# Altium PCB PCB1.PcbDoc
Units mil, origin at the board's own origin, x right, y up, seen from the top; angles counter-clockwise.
Board outline 5505 x 1975 mil, 4 copper layers (SIG_1, GND, GND-PWR, SIG_2), stack 23.712 mil thick; 82 components, 46 nets, 222 pads, 73 vias.
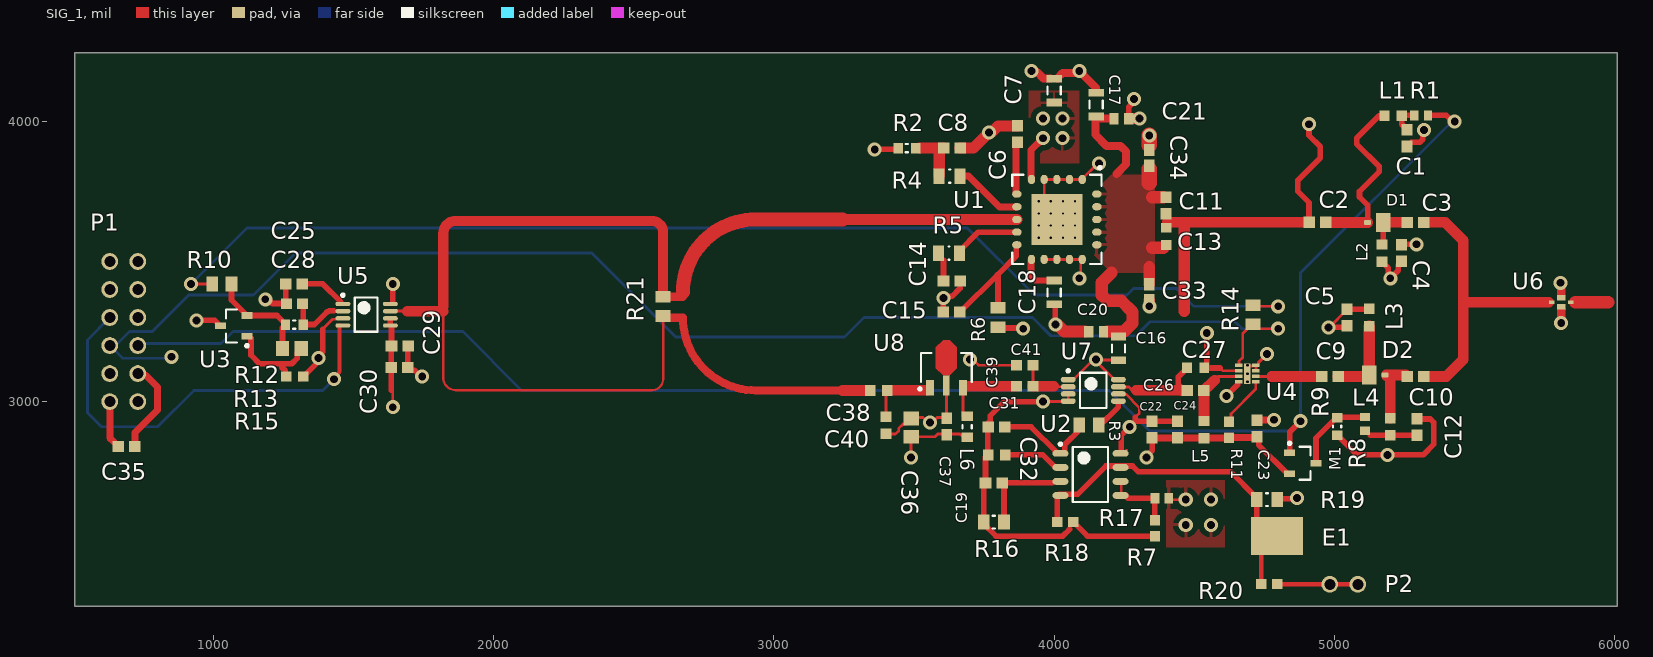
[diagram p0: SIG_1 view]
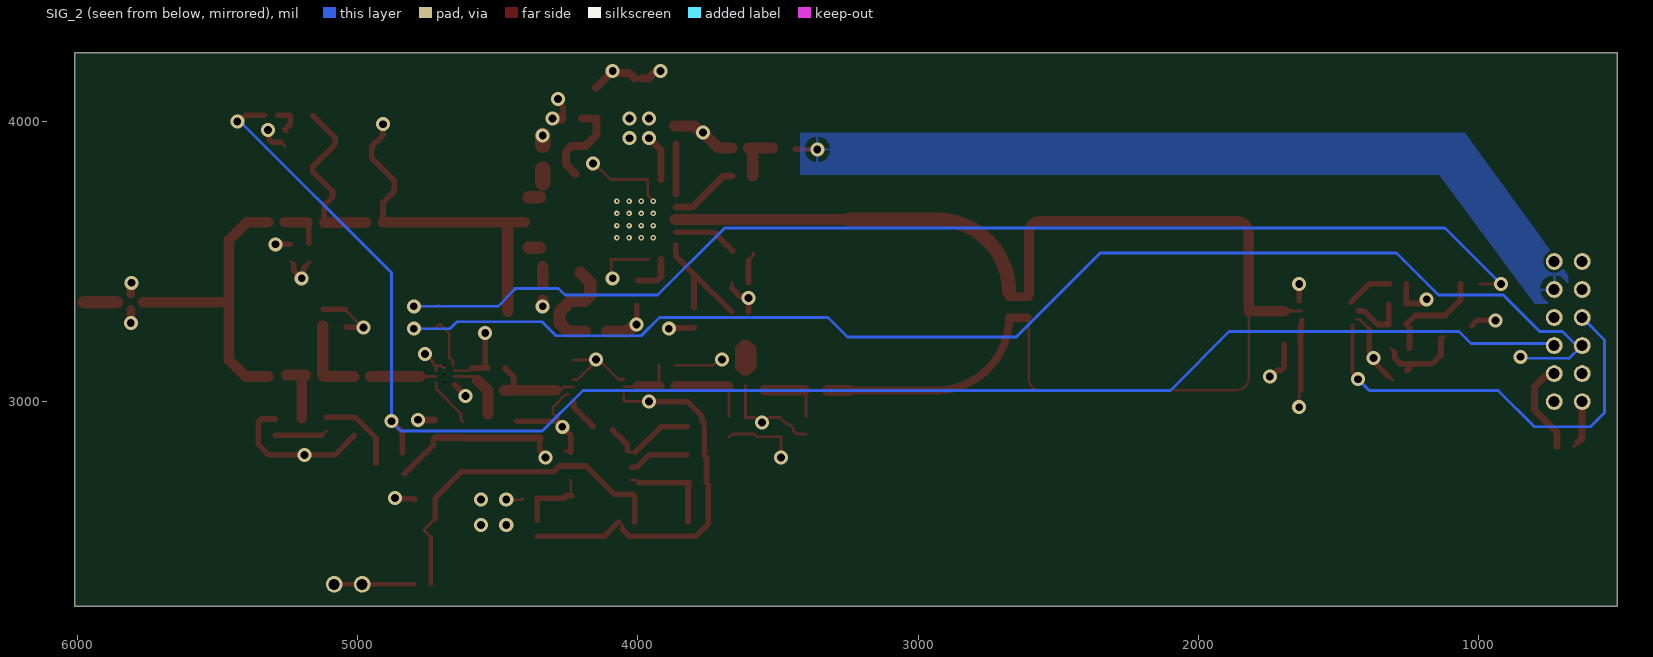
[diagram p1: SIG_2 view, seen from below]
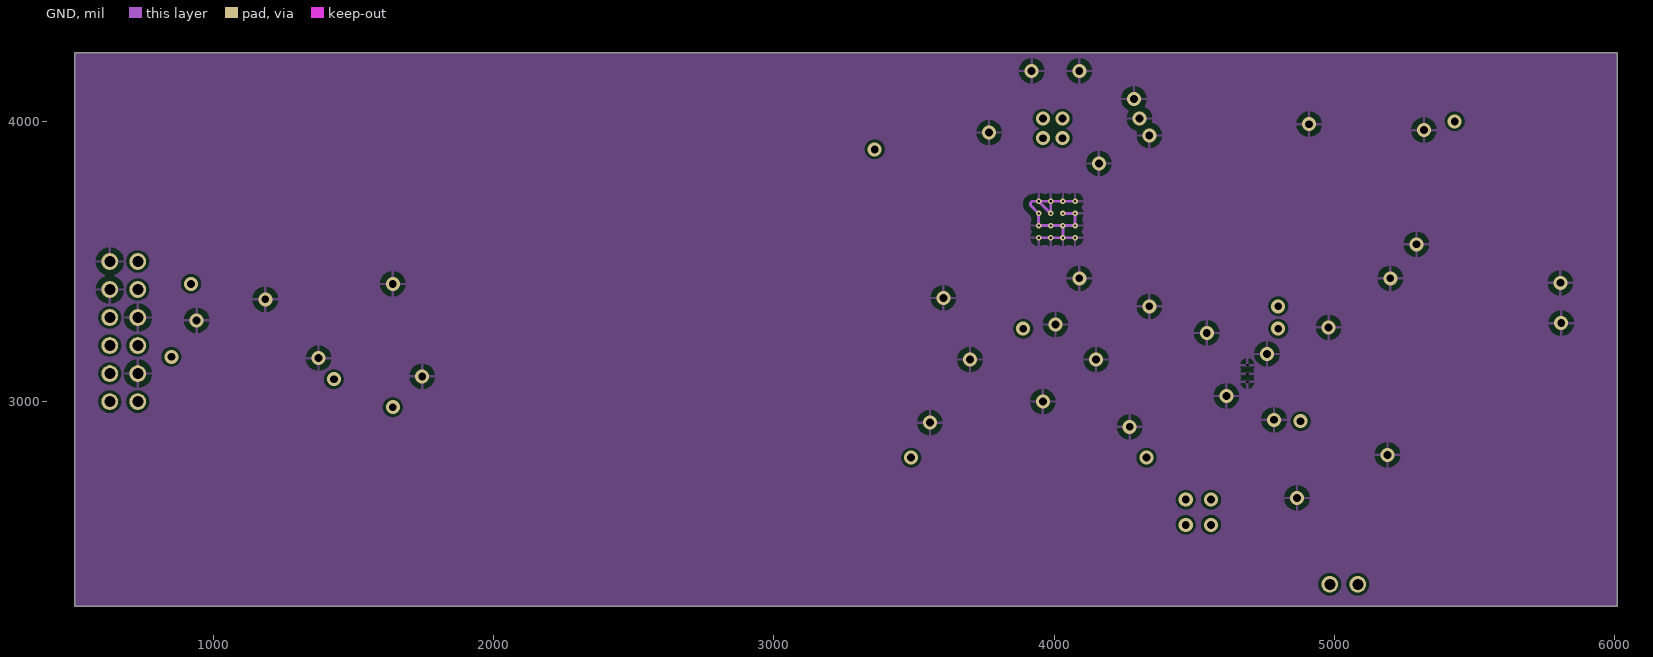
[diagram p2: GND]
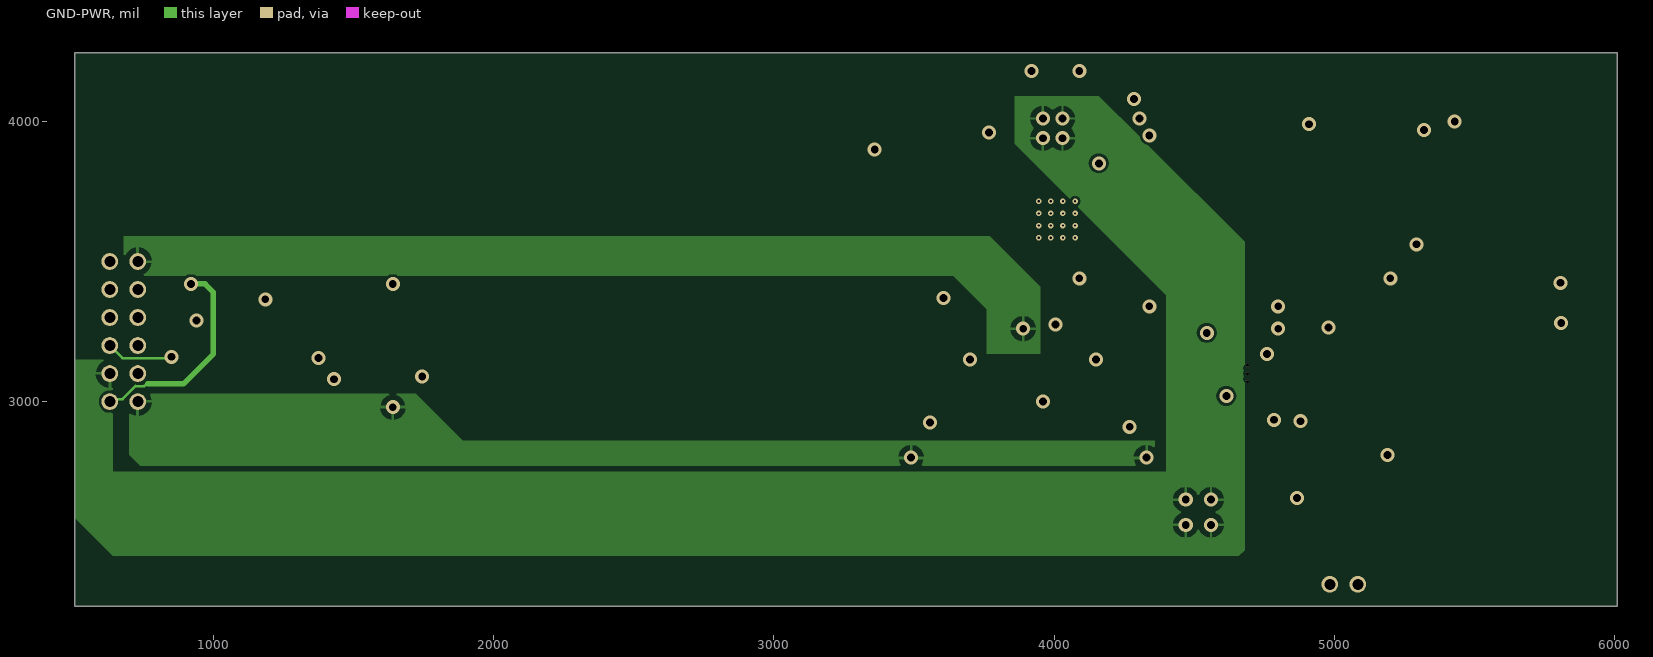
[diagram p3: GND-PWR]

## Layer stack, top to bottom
SIG_1: signal copper 1.378
Dielectric 2: prepreg 2.8, PP-006, Dk 4.1
GND: signal copper 1.378
Dielectric 1: dielectric 12.6, FR-4, Dk 4.8
GND-PWR: signal copper 1.378
Dielectric 3: prepreg 2.8, PP-006, Dk 4.1
SIG_2: signal copper 1.378

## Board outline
505,2270 505,4245 6010,4245 6010,2270

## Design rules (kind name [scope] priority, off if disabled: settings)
Clearance Clearance_1 [All] p1: gap=10 ignorepadtopadclearanceinfootprint=TRUE except(0: Arc-Hole Track-Hole SMDPad-Hole THPad-Hole Via-Hole Fill-Hole Poly-Hole Region-Hole Text-Hole; 5: Arc-SMDPad Track-SMDPad SMDPad-SMDPad SMDPad-Text Fill-Text Poly-Text Region-Text; 6: THPad-Via Via-Via; 20: Arc-Fill Arc-Poly Arc-Region Track-Fill Track-Poly Track-Region SMDPad-Fill SMDPad-Poly SMDPad-Region Fill-Fill Fill-Poly Fill-Region Poly-Poly Poly-Region Region-Region)
PlaneConnect [All] p1: planeconnectstyle=Direct reliefexpansion=20 reliefentries=4 reliefconductorwidth=10 reliefairgap=20
PolygonConnect [All] p1: connectstyle=Relief reliefconductorwidth=10 reliefentries=4 polygonreliefangle="90 Angle" airgapwidth=20
RoomDefinition 33-1-001_R01 [InComponentClass('33-1-001_R01')] p1 off: confinementstyle=ConfineIn formatcopy=TRUE lockcomponents=FALSE outline 8825,45 14100,45 14100,2135 8825,2135
RoutingVias [All] p1: holewidth=28 width=50 viastyle="Through Hole" minholewidth=28 minwidth=50 maxholewidth=28 maxwidth=50
SilkToSilkClearance [All] p1: silktosilkclearance=5
SilkToSolderMaskClearance [IsPad] p1: minsilkscreentomaskgap=5 clearancetoexposedcopper=TRUE
SolderMaskExpansion [All] p1: expansion=4 istentingtop=FALSE
Width [All] p1: maxlimit=200 minlimit=5 preferedwidth=10
27 further rules are at their usual default settings.

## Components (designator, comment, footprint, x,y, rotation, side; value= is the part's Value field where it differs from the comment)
C1 "C00000013" C0603C101J5GAC7082 5260,3940 r270 top
C2 "C00000013" C0603C101J5GAC7082 4940,3640 r0 top
C3 "C00000013" C0603C101J5GAC7082 5289.53,3639.53 r0 top
C4 "C00000013" C0603C101J5GAC7082 5240,3530 r270 top
C5 "C00000013" C0603C101J5GAC7082 5045,3299.53 r270 top
C6 "C00000007" 06033D105KAT2A 3870,3954.53 r90 top
C7 "C00000003" C2012X5R1V106K125AC 4000,4110 r90 top
C8 "C00000007" 06033D105KAT2A 3635.47,3905 r0 top
C9 "C00000013" C0603C101J5GAC7082 4985,3089.53 r0 top
C10 "C00000013" C0603C101J5GAC7082 5289.53,3089.53 r0 top
C11 "C00000007" 06033D105KAT2A 4400,3700 r90 top
C12 "C00000013" C0603C101J5GAC7082 5295,2909.25 r90 top
C13 "C00000005" CBR06C508A5GAC 4400,3590 r90 top
C14 "C00000007" 06033D105KAT2A 3635,3430 r180 top
C15 "C00000007" 06033D105KAT2A 3634.53,3320 r0 top
C16 "C00000003" C2012X5R1V106K125AC 4230,3190 r90 top
C17 "C00000003" C2012X5R1V106K125AC 4150,4060 r270 top
C18 "C00000003" C2012X5R1V106K125AC 4000,3390 r90 top
C19 "C00000011" C0603C104K4RACTU 3785,2710 r0 top
C20 "C00000004" 06035U9R1BAT2A 4150,3250 r0 top
C21 "C00000004" 06035U9R1BAT2A 4240,4010 r180 top
C22 "C00000007" 06033D105KAT2A 4350,2900 r270 top
C23 "C00000013" C0603C101J5GAC7082 4725,2904.53 r270 top
C24 "C00000013" C0603C101J5GAC7082 4440,2900 r90 top
C25 "C00000011" C0603C104K4RACTU 1286.89,3420 r180 top
C26 "C00000008" GQM1875C2E1R6BB12D 4505,3040 r180 top
C27 "C00000005" CBR06C508A5GAC 4505.51,3120 r180 top
C28 "C00000001" C0603C184J3RACTU 1288.86,3350 r0 top
C29 "C00000012" C0603C221J3RACAUTO 1665,3197.63 r180 top
C30 "C00000012" C0603C221J3RACAUTO 1664.53,3121.97 r180 top
C31 "C00000007" 06033D105KAT2A 3795,2910 r0 top
C32 "C00000014" ML03510R8BAT2A 3795,2810 r0 top
C33 "C00000010" VJ0603D1R8BXCQJHT 4340,3390 r90 top
C34 "C00000010" VJ0603D1R8BXCQJHT 4340,3870 r270 top
C35 "C00000011" C0603C104K4RACTU 690,2840 r180 top
C36 "C00000017" EMK212B7105KG-T 3490,2907.05 r270 top
C37 "C00000016" C0603C102F4GACTU 3617,2911 r270 top
C38 "C00000014" ML03510R8BAT2A 3375,3040 r0 top
C39 "C00000015" VJ0603A1R5CXQCW1BC 3895,3055 r0 top
C40 "C00000014" ML03510R8BAT2A 3400,2915 r90 top
C41 "C00000015" VJ0603A1R5CXQCW1BC 3895,3130 r0 top
D1 "D00000001" SMP1334-084LF 5140,3640 r180 top
D2 "D00000001" SMP1334-084LF 5160,3094 r0 top
E1 "5016" 5016 4795.43,2520 r0 top
L1 "L00000001" ILC0603ER22NJ 5210,4020 r0 top
L2 "L00000001" ILC0603ER22NJ 5170,3530 r90 top
L3 "L00000001" ILC0603ER22NJ 5125,3300 r90 top
L4 "L00000001" ILC0603ER22NJ 5200,2910.24 r90 top
L5 "L00000001" ILC0603ER22NJ 4535,2900 r270 top
L6 "L00000002" LQW18AS8N7J00D 3690,2910 r270 top
M1 "BSS84" BSS84,215 4887.76,2780 r0 top
P1 "67997-112HLF" 67997-112HLF 630,3000 r90 top
P2 "2Pin_Header" 2Pin_Header 4984,2348 r0 top
R1 "R00000009" CR0603-JW-820ELF 5310,4021.57 r0 top
R2 "R00000008" ERJ-U3RD8200V 3475,3905 r0 top
R3 "R00000003" SFR10EZPF10R0 4125,2916.7 r180 top
R4 "R00000004" CRCW08055R10FKTA 3627.6,3805 r0 top
R5 "R00000004" CRCW08055R10FKTA 3625,3530 r0 top
R6 "R00000003" SFR10EZPF10R0 3800,3300 r90 top
R7 "R00000011" ESR03EZPJ432 4360,2548.54 r90 top
R8 "R00000009" CR0603-JW-820ELF 5110,2920.08 r90 top
R9 "R00000001" ERJ-UP3F8660V 5010,2911.22 r90 top
R10 "R00000005" CR0805-FX-1580ELF 1030,3420 r180 top
R11 "R00000011" ESR03EZPJ432 4625,2900 r270 top
R12 "R00000006" ERA-6AEB101V 1280,3190 r180 top
R13 "R00000001" ERJ-UP3F8660V 1288.86,3275 r180 top
R14 "R00000010" CR0805-JW-203ELF 4710,3310 r90 top
R15 "R00000007" "RN73H1JTTD43R7B25 - duplicate" 1290,3090 r180 top
R16 "R00000012" RK73H2ATTD3832F 3785,2570 r0 top
R17 "R00000013" RCS0603499RFKEA 4385,2655 r180 top
R18 "R00000011" ESR03EZPJ432 4040,2570 r180 top
R19 "R00000012" RK73H2ATTD3832F 4760,2650 r0 top
R20 "R00000011" ESR03EZPJ432 4768,2349 r180 top
R21 "R00000010" CR0805-JW-203ELF 2605,3340 r90 top
U1 "IC BLM9D2327-26B" BLM9D2327-26B 4010,3650 r270 top
U2 "IC LM2907" LM2907 4130,2740 r0 top
U3 "IC TL4051AQDBZR" TL4051AQDBZR 1072.24,3270 r180 top
U4 "IC QPL9503" QPL9503 4716.57,3117.72 r180 top
U5 "IC MAX 2750 VCO" MAX2750EUA+ 1530,3310 r0 top
U6 "DEA162495BT-1289A1" DEA162495BT-1289A1 5810,3355 r0 top
U7 "IC HMC213BMS8E" HMC213BMS8E 4140,3040 r0 top
U8 "SKY65162-70LF" SKY65162-70LF 3615.94,3120.87 r90 top

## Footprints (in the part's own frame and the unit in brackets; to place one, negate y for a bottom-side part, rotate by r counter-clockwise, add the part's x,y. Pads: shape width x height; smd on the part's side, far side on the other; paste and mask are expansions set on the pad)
2Pin_Header [mil] "2Pin"
  round 60 hole 39.37: 1(0,0) 2(100,0)
5016 [mm] "Test point"
  rect 4.7x3.43 smd: 1(0,0)
06033D105KAT2A [mm] "Multilayer Ceramic Capacitors MLCC - SMD/SMT 25V 1uF X5R 0603 10%"
  rect 1.05x1 smd: 1(-0.75,0) 2(0.75,0)
  body extent -0.88,-0.48 0.87,0.48, height 0.8
06035U9R1BAT2A [mm] "Multilayer Ceramic Capacitors MLCC - SMD/SMT 50V 9.1pF C0G 0603 0.1pF"
  rect 0.84x1.04 smd: 1(-0.67,0) 2(0.67,0)
  body extent -0.89,-0.51 0.88,0.5, height 0.91
67997-112HLF [mil] "12 Pos. 2 Row Conn."
  round 60 hole 39.37: 1(0,0) 2(100,0) 3(200,0) 4(300,0) 5(400,0) 6(500,0) 7(0,-100) 8(100,-100) 9(200,-100) 10(300,-100) 11(400,-100) 12(500,-100)
BLM9D2327-26B [mm] "LDMOS 2-stage integrated Doherty MMIC"
  oval 0.85x0.65 smd: 1(-3.625,2.3) 2(-3.625,1.15) 3(-3.625,0) 4(-3.625,-1.15) 5(-3.625,-2.3) 11(3.625,-2.3) 12(3.625,-1.15) 13(3.625,0) 14(3.625,1.15) 15(3.625,2.3)
  oval 0.65x0.85 smd: 6(-2.3,-3.625) 7(-1.15,-3.625) 8(0,-3.625) 9(1.15,-3.625) 10(2.3,-3.625) 16(2.3,3.625) 17(1.15,3.625) 18(0,3.625) 19(-1.15,3.625) 20(-2.3,3.625)
  rect 4.62x4.62 smd: 21(0,0)
  silkscreen extent -4.82,-4.05 4.05,4.05, body extent -4.05,-4.05 4.05,4.05, height 2.2
BSS84,215 [mm] "MOSFET P-CH DMOS 50V 130MA"
  rect 1x0.6 smd: 1(-1.2,0.95) 2(-1.2,-0.95) 3(1.2,0)
  silkscreen extent -1.32,-1.5 0.7,1.92, body extent -0.7,-1.5 0.7,1.5, height 1.1
C0603C101J5GAC7082 [mm] "MLCC - SMD/SMT 50V 100pF 0603 C0G 0.05"
  rect 1.05x1 smd: 1(-0.75,0) 2(0.75,0)
  body extent -0.88,-0.48 0.87,0.47, height 0.8
C0603C102F4GACTU [mm] "MLCC - SMD/SMT 16V 1000pF 0603 C0G 0.01"
  rect 1.05x0.95 smd: 1(-0.75,0) 2(0.75,0)
  body extent -0.88,-0.45 0.87,0.45, height 0.94
C0603C104K4RACTU [mm] "MLCC - SMD/SMT 16V 0.1uF X7R 0603 10%"
  rect 1.05x1 smd: 1(-0.75,0) 2(0.75,0)
  body extent -0.88,-0.48 0.87,0.47, height 0.8
C0603C184J3RACTU [mm] "Multilayer Ceramic Capacitors MLCC - SMD/SMT 25V 0.18uF X7R 0603 5%"
  rect 1x0.95 smd: 1(-0.725,0) 2(0.725,0)
  body extent -0.87,-0.48 0.87,0.48, height 0.8
C0603C221J3RACAUTO [mm] "MLCC - SMD/SMT 25V 220pF X7R 0603 5% AEC-Q200"
  rect 1.05x1 smd: 1(-0.75,0) 2(0.75,0)
  body extent -0.88,-0.48 0.87,0.47, height 0.8
C2012X5R1V106K125AC [mm] "Multilayer Ceramic Capacitors MLCC - SMD/SMT 0805 35V 10uF X5R 10% T: 1.25mm"
  rect 0.7x1.4 smd: 1(-1.075,0) 2(1.075,0)
  silkscreen extent -0.35,-0.6 0.35,0.6, body extent -1,-0.63 1,0.63, height 1.25
CBR06C508A5GAC [mm] "Multilayer Ceramic Capacitors MLCC - SMD/SMT 50V 0.5pF C0G 0603 0.05pF"
  rect 0.9x0.95 smd: 1(-0.775,0) 2(0.775,0)
  body extent -0.85,-0.45 0.85,0.45, height 0.87
CR0603-JW-820ELF [mm] "Thick Film Resistors - SMD 82 OHM 5%"
  rect 0.75x0.9 smd: 1(-0.625,0) 2(0.625,0)
  body extent -0.8,-0.45 0.8,0.45, height 0.8
CR0805-FX-1580ELF [mm] "Thick Film Resistors - SMD 158ohm 1%"
  rect 1.05x1.35 smd: 1(-0.875,0) 2(0.875,0)
  body extent -1.05,-0.67 1.05,0.67, height 0.6
CR0805-JW-203ELF [mm] "Thick Film Resistors - SMD 20K 5%"
  rect 1.05x1.35 smd: 1(-0.875,0) 2(0.875,0)
  body extent -1.05,-0.67 1.05,0.67, height 0.6
CRCW08055R10FKTA [mm] "Thick Film Resistors - SMD 1/8watt 5.1ohms 1%"
  rect 1x1.4 smd: 1(-0.95,0) 2(0.95,0)
  silkscreen extent -0.05,-0.6 0.05,0.6, body extent -1.1,-0.7 1.1,0.7, height 0.5
DEA162495BT-1289A1 [mm] "Multilayer Band Pass Filter  For 2300-2690MHz"
  rect 0.5x0.3 smd: 1(0.85,0) 3(-0.85,0)
  rect 0.8x0.5 smd: 2(0,-0.4) 4(0,0.4)
EMK212B7105KG-T [mm] "MLCC - SMD/SMT 0805 16VDC 1uF 10% X7R"
  rect 1.25x1.4 smd: 1(-0.825,0) 2(0.825,0)
  body extent -1.05,-0.67 1.05,0.67, height 0.94
ERA-6AEB101V [mm] "Thin Film Resistors - SMD 0805 1/8W 100ohms"
  rect 1.2x1.35 smd: 1(-0.85,0) 2(0.85,0)
  body extent -1.1,-0.67 1.1,0.67, height 0.6
ERJ-U3RD8200V [mm] "Thick Film Resistors - SMD 0603 Anti-sulfur"
  rect 0.85x0.95 smd: 1(-0.8,0) 2(0.8,0)
  silkscreen extent -0.1,-0.38 0.1,0.38, body extent -0.88,-0.48 0.87,0.48, height 0.55
ERJ-UP3F8660V [mm] "Thick Film Resistors - SMD 0603 0.25W 1% 866ohm AEC-Q200"
  rect 0.85x0.95 smd: 1(-0.8,0) 2(0.8,0)
  silkscreen extent -0.1,-0.38 0.1,0.38, body extent -0.88,-0.48 0.87,0.48, height 0.55
ESR03EZPJ432 [mm] "Thick FilmResistors - SMD 0603 4.3Kohm 5% Anti Surge AEC-Q200"
  rect 0.95x0.9 smd: 1(-0.725,0) 2(0.725,0)
  body extent -0.85,-0.45 0.85,0.45, height 0.55
GQM1875C2E1R6BB12D [mm] "Multilayer Ceramic Capacitors MLCC - SMD/SMT 0603 1.6pF 250volts C0G 0.1pF"
  rect 1.05x1 smd: 1(-0.75,0) 2(0.75,0)
  body extent -0.88,-0.48 0.87,0.47, height 0.8
HMC213BMS8E [mm] "1.5 GHz to 4.5 GHz, GaAs, MMIC,  Double Balanced Mixer"
  oval 1.35x0.5 smd: 1(-2.275,0.975) 2(-2.275,0.325) 3(-2.275,-0.325) 4(-2.275,-0.975) 5(2.275,-0.975) 6(2.275,-0.325) 7(2.275,0.325) 8(2.275,0.975)
  silkscreen extent -2.4,-1.6 1.2,1.9, body extent -1.6,-1.6 1.6,1.6, height 1.1
ILC0603ER22NJ [mm] "Fixed Inductors 22nH 5%"
  rect 0.94x0.98 smd: 1(-0.78,0) 2(0.78,0)
  body extent -0.88,-0.48 0.87,0.47, height 0.8
LM2907 [mm] "Frequency to Voltage Converter"
  oval 1.45x0.6 smd: 1(-2.725,1.905) 2(-2.725,0.635) 3(-2.725,-0.635) 4(-2.725,-1.905) 5(2.725,-1.905) 6(2.725,-0.635) 7(2.725,0.635) 8(2.725,1.905)
  silkscreen extent -2.85,-2.5 1.6,2.88, body extent -2,-2.5 2,2.5, height 1.75
LQW18AS8N7J00D [mm] "8.7nH 0603"
  rect 0.87x1.03 smd: 1(-0.94,0) 2(0.94,0)
  silkscreen extent -0.15,-0.42 0.15,0.42, body extent -1,-0.5 1,0.5, height 0.94
MAX2750EUA+ [mm] "VCO Oscillators 2.4Ghz Monolithic Voltage-Controlled Oscillators"
  oval 1.35x0.4 smd: 1(-1.725,0.975) 2(-1.725,0.325) 3(-1.725,-0.325) 4(-1.725,-0.975) 5(2.575,-0.975) 6(2.575,-0.325) 7(2.575,0.325) 8(2.575,0.975)
  silkscreen extent -1.85,-1.55 1.4,1.9, body extent -1.55,-1.55 2.41,1.55, height 1.1
ML03510R8BAT2A [mm] "MLCC - SMD/SMT 50V 0.8pF C0G 0603 0.1pF"
  rect 0.95x1 smd: 1(-0.775,0) 2(0.775,0)
  body extent -0.85,-0.47 0.85,0.47, height 0.94
QPL9503 [mm] "Ultra Low-Noise, Flat Gain LNA"
  rect 0.674x0.3 smd: 1(-0.1,1.2) 2(-0.1,0.7) 3(-0.1,0.2) 4(-0.1,-0.3) 5(1.45,-0.3) 6(1.45,0.2) 7(1.45,0.7) 8(1.45,1.2)
  rect 0.6x1.85 smd: 4(0.675,0.465)
RCS0603499RFKEA [mm] "Thick Film Resistors - SMD 0.25watt 499ohms 1% 100ppm"
  rect 0.8x0.95 smd: 1(-0.625,0) 2(0.625,0)
  body extent -0.82,-0.48 0.82,0.48, height 0.5
RK73H2ATTD3832F [mm] "Thick Film Resistors - SMD 1/4W 38.3K OHM 1%"
  rect 1.05x1.35 smd: 1(-0.925,0) 2(0.925,0)
  silkscreen extent -0.1,-0.58 0.1,0.58, body extent -1.1,-0.67 1.1,0.67, height 0.6
"RN73H1JTTD43R7B25 - duplicate" [mm] "Chip Resistor, 2-Leads, Body 1.60x0.80mm, IPC Medium Density"
  rect 0.95x0.9 smd: 1(-0.775,0) 2(0.775,0)
  body extent -0.9,-0.45 0.9,0.45, height 0.55
SFR10EZPF10R0 [mm] "Thick Film Resistors - SMD 10ohm 0805 1%"
  rect 1.05x1.35 smd: 1(-0.875,0) 2(0.875,0)
  body extent -1.05,-0.67 1.05,0.67, height 0.65
SKY65162-70LF [mm] "RF Amplifier 400-2700MHz NF 3.6dB Gain 24dB"
  rect 1.4x0.7 smd: 1(-1.8,1.5) 3(-1.8,-1.5)
  rect 1.8x0.6 smd: 2(-1.6,0)
  SIG_1 region: -0.7,0.3 -0.05,0.95 1.85,0.95 2.5,0.3 2.5,-0.3 1.85,-0.95 -0.05,-0.95 -0.7,-0.3
  silkscreen extent -2.05,-2.3 1.32,2.52, body extent -1.28,-2.3 1.32,2.3, height 1.6
SMP1334-084LF [mil] "100 W High-Power Silicon PIN Diode"
  rect 53.15x68.9 smd: 1(-35,1)
  rrect50% 25.59x17.72 smd: 2(21,1)
TL4051AQDBZR [mm] "Voltage References Precision Micropower Shunt Vltg Ref"
  rect 1x0.6 smd: 1(-1.2,0.95) 2(-1.2,-0.95) 3(1.2,0)
  silkscreen extent -1.33,-1.5 0.7,1.92, body extent -0.7,-1.52 0.7,1.52, height 1.1
VJ0603A1R5CXQCW1BC [mm] "MLCC - SMD/SMT 0603 1.5pF 10volts C0G +/-0.25pF"
  rect 1x0.95 smd: 1(-0.75,0) 2(0.75,0)
  body extent -0.85,-0.45 0.85,0.45, height 0.94
VJ0603D1R8BXCQJHT [mm] "Multilayer Ceramic Capacitors MLCC - SMD/SMT 1.8pF 200V 0.1% C0G"
  rect 1.1x0.95 smd: 1(-0.725,0) 2(0.725,0)
  body extent -0.87,-0.46 0.87,0.46, height 0.94

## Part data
C1 C2 C3 C4 C5 C9 C10 C12 C23 C24: "MLCC 100pF 5% 50V 0603", Capacitance=100pF, Dielectric=C0G, Package=0603, Tolerance=5%, Voltage=50V
C6 C8 C11 C14 C15 C22 C31: "MLCC 1uF 25V X5R 0603", Capacitance=1uF, Dielectric=X5R, Package=0603, Tolerance=10%, Voltage=25V
C7 C16 C17 C18: "MLCC 10uF 35V X5R 0805", Capacitance=10uF, Dielectric=X5R, Package=0805, Tolerance=20%, Voltage=35V
C13 C27: "MLCC 0.5pF 50V 0603 C0G", Capacitance=0.5pF, Dielectric=C0G, Package=0603, Tolerance=0.05pF, Voltage=50V
C19 C25 C35: "MLCC 0.1uF 16V 0603 X7R", Capacitance=0.1uF, Dielectric=X7R, Package=0603, Tolerance=10%, Voltage=16V
C20 C21: "MLCC 9.1pF 50V 0603 C0G", Capacitance=9.1pF, Dielectric=C0G, Package=0603, Tolerance=0.1pF, Voltage=50V
C26: "MLCC 5.6pF 250V C0G 0603", Capacitance=5.6pF, Dielectric=C0G, Package=0603, Tolerance=20%, Voltage=250V
C28: "MLCC 180nF 25V X7R 0603", Capacitance=180nF, Dielectric=X7R, Package=0603, Tolerance=5%, Voltage=25V
C29 C30: "MLCC 220pF 5% 25V 0603 X7R", Capacitance=220pF, Dielectric=X7R, Package=0603, Tolerance=5%, Voltage=25V
C32 C38 C40: "Capacitors MLCC - SMD/SMT 50V 0.8pF C0G 0603 0.1pF", Capacitance=0.8pF, Dielectric=C0G, Package=0603, Tolerance=0.1pF, Voltage=50V
C33 C34: "MLCC 1.8 pF 250V C0G 0603", Capacitance=1.8pF, Dielectric=C0G, Package=0603, Tolerance=0.1pF, Voltage=200V
C36: "MLCC - SMD/SMT 10V 1uF X7R 0805 10% / RoHS Compliant", Capacitance=1uF, Dielectric=X7R, Package=0805, Tolerance=5%, Voltage=10V
C37: "MLCC - SMD/SMT 16V 1000pF 0603 C0G 0.01", Capacitance=1000pF, Dielectric=C0G, Package=0603, Tolerance=5%, Voltage=16V
C39 C41: "MLCC - SMD/SMT 0603 1.5pF 10volts C0G +/-0.25p", Capacitance=1.5pF, Dielectric=C0G, Package=0603, Tolerance=5%, Voltage=10V
D1 D2: "PIN DIODE .45 Pf .45 OHM .37 nH, 1-8GHz, SMP1334-084LF"
E1: "SMD test point"
L1 L2 L3 L4 L5: "22nH 300mA 0603 RF Inductor", Inductance=22nH, Package=0603
L6: "IND 8.7nH 550mA 0603", Inductance=8.7nH, Package=0603
M1: "MOSFET P-CH DMOS 50V 130MA"
R1 R8: "RES CHIP 82E 5% 1/10W", Package=0603, Power=1/10W, Resistance=82E, Tolerance=1%, Voltage Rating=50V
R2: "RES CHIP 820E 1%", Package=0603, Power=1/4W, Resistance=820E, Tolerance=1%, Voltage Rating=150
R3 R6: "RES CHIP 10E 0805 1%", Package=0805, Resistance=10E, Tolerance=1%
R4 R5: "RES CHIP 5.1E 0805 1%", Package=0805, Power=1/8W, Resistance=5.1E, Tolerance=1%, Voltage Rating=150V
R7 R11 R18 R20: "RES CHIP 4.3k 5% 0603 ESR03EZPJ432", Package=0603, Power=1/4W, Resistance=4.3k, Tolerance=5%, Voltage Rating=150V
R9 R13: "RES CHIP 866 0603 1%", Package=0603, Power=1/4W, Resistance=866E, Tolerance=1%, Voltage Rating=150V
R10: "RES CHIP 158E 0805 1%", Package=0805, Power=1/8W, Resistance=158E, Tolerance=1%, Voltage Rating=150V
R12: "RES CHIP 100E 0.1%", Package=0805, Power=1/8W, Resistance=100E, Tolerance=0.1%, Voltage Rating=100V
R14 R21: "RES CHIP 20k 5% / CR0805-JW-203ELF", Package=0805, Power=1/8W, Resistance=20k, Tolerance=5%, Voltage Rating=150V
R15: "RES CHIP 43.7E 0603 0.1%", Package=0603, Power=1/10W, Resistance=43.7E, Tolerance=0.1%, Voltage Rating=75V
R16 R19: "RES CHIP 38.3k 1% 0805", Package=0805, Power=1/4W, Resistance=38.3k, Tolerance=1%, Voltage Rating=150V
R17: "RES CHIP 499E 1% 0603 75V", Package=0603, Power=1/4W, Resistance=499E, Tolerance=1%, Voltage Rating=75V
U1: "LDMOS 2-stage integrated Doherty MMIC"
U3: "Precision voltage reference"
U5: "2.4-2.5 GHz VCO"
U6: "2.5GHz BPF"
U8: "SKY65162-70LF: 400 to 3800 MHz Linear Power Amplifier."

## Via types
v1: diameter 50, hole 28, SIG_1 to SIG_2, 54 vias
v2: diameter 19.68, hole 7.87, SIG_1 to SIG_2, 16 vias
v3: diameter 10, hole 10, SIG_1 to SIG_2, 3 vias

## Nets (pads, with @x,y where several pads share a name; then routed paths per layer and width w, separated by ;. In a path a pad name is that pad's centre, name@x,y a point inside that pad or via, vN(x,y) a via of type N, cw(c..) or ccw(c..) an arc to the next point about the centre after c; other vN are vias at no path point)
GND: C1.2 C4.1 C4.2 C5.1 C5.2 C6.2 C7.2 C8.2 C12.2 C14.1 C15.1 C16.1 C17.1 C18.1 C19.1 C20.1 C21.1 C22.1 C23.1 C24.2 C25.2 C27.1 C28.1 C29.1 C30.1 C31.1 C32.1 C33.1 C34.1 C35.1 C36.1 C37.1 C40.1 C41.1 L2.1 L3.2 P1.5 P1.6 P1.8 P1.10 R7.1 R9.1 R15.1 R16.1 R18.1 R19.2 U1.1 U1.2 U1.3 U1.4 U1.12 U1.13 U1.14 U1.15 U1.21 U2.8 U3.3 U4.3 U4.4 U4.6 U4.8 U5.3 U5.8 U6.2 U6.4 U7.1 U7.3 U7.4 U7.6 U7.8 U8.2 | length 7765.4
  SIG_1 w10: v1(1185,3365) v1@1195.82,3365 ; C25.2@1255.47,3420 C25.2@1257.44,3421.97 ; C28.1@1257.36,3352.95 C28.1 ; R15.1@1306.46,3075.95 R15.1 R15.1@1321.5,3090 ; v1@1367.35,3135.85 1367.35,3147.35 v1(1375,3155) ; 1390,3258.56 1425.11,3293.66 1433.43,3293.66 ; v1@1740,3090 v1(1745,3090) ; C40.1 3434.69,2884.49 3445.46,2895.26 3445.46,2903.4 3461.98,2919.92 3470.39,2919.92 3493.47,2943 3532.56,2943 3550.56,2925 3565.3,2925 3583.3,2943 3614.53,2943 C37.1 ; C15.1@3604.02,3320 C15.1 ; C37.1@3615.94,2939.53 U8.2 ; 3664.53,3404.53 C14.1@3664.53,3425 ; v1(3700,3150) 3710.82,3150 3730.82,3130 C41.1 ; R16.1@3748.58,2564.09 R16.1 ; C19.1@3748.58,2703.11 C19.1 ; C32.1@3755.47,2801.97 C32.1@3763.5,2810 ; C31.1 C31.1@3765.47,2924.53 ; v1(3767.97,3960.03) v1@3776.5,3960.03 ; v2(3945.04,3714.96) 3964.72,3734.65 U1.4@3964.72,3792.44 ; v1(3960,3000) 3960.81,3000.81 4049.63,3000.81 U7.4 U7.3 ; U1.12@3962.44,3507.01 4098.27,3507.01 4095.28,3504.02 4095.28,3445.28 v1(4090,3440) ; U1.4 U1.4@3964.72,3792.44 ; C18.1 C18.1@4004.82,3342.85 ; v1(4004.82,3275.18) v1@4007.93,3275.18 ; v1@4004.82,3278.28 v1@4007.93,3275.18 ; v1@4011.04,3275.18 v1@4007.93,3275.18 ; U7.1 4069.79,3078.39 4141.4,3150 v1(4150,3150) ; 4055,2544.13 4055,2557.28 4067.72,2570 R18.1 R18.1@4069.53,2570 ; v1@4083,4173 v1(4090,4180) ; v1(4160,3850) 4155.94,3850 4098.39,3792.44 U1.4@3964.72,3792.44 ; C16.1@4216.22,3147.68 C16.1 4228.84,3148.84 4151.16,3148.84 v1(4150,3150) ; U7.8 4215.46,3078.39 4150,3143.84 v1(4150,3150) ; U7.6@4250,3026.46 4256.59,3026.46 4303.79,2979.26 4303.79,2957.93 4289.53,2943.67 ; U2.8@4252.61,2820 4258.91,2826.29 ; v1(4270,2910) 4289.53,2929.53 ; v1@4285,4069.18 v1(4285,4080) ; C22.1 C22.1@4350.47,2930 ; C24.2@4430,2930 4430.47,2929.53 C24.2 ; C27.1 C27.1@4545,3128.98 ; 4592.4,3120 4602.56,3109.84 U4.6@4654.49,3109.84 ; U4.4@4690,3119.69 4696.81,3126.5 4710.12,3126.5 4713.15,3129.53 U4.4@4720.51,3129.53 ; U4.3 U4.4@4720.51,3129.53 ; C23.1 C23.1@4725.94,2935 ; v1@4760,3168.73 v1(4760,3170) 4728.78,3138.78 4728.78,3130.43 4727.87,3129.53 U4.4@4720.51,3129.53 ; v1(4980,3265) 4981.93,3265 5045,3328.07 C5.1 ; R9.1@5008.03,2879.72 R9.1 R9.1@5011.97,2879.72 ; C5.2@5040,3265 C5.2 ; L3.2@5123.35,3329.06 L3.2 ; L2.1 5170.79,3499.29 5184.29,3485.79 L2.1@5184.29,3485 ; v1@5192.35,3447.65 v1(5200,3440) ; C4.2@5228.28,3488.76 C4.2 ; C4.1 C4.1@5241.76,3561.29 ; C1.2 5260,3911.46 C1.2@5274.69,3926.14 ; C12.2@5295,2937.8 C12.2 ; v1@5316.14,3965 v1(5320,3968.86) ; U6.2@5810,3330 U6.2
  SIG_1 w20: v1(940,3290) 1005,3290 U3.3 ; v1@1195.82,3365 1210.82,3350 C28.1 ; C28.1@1257.36,3352.95 C25.2 ; R15.1@1321.5,3090 v1@1367.35,3135.85 ; v1(1375,3155) 1375,3163.12 1390,3178.12 1390,3258.56 ; 1640,3360 v1(1640,3420) ; C29.1@1694.06,3204.53 C30.1 1703.74,3112.28 1717.72,3112.28 v1@1740,3090 ; C15.1@3606.2,3320.21 3605,3321.41 v1(3605,3370) 3610.74,3375.74 3635.74,3375.74 3664.53,3404.53 ; R16.1@3748.58,2564.09 3792.68,2520 4030.87,2520 4055,2544.13 ; R16.1 C19.1@3748.58,2703.11 ; C19.1 C32.1@3755.47,2801.97 ; C32.1@3763.5,2810 C31.1@3763.5,2908.03 ; C31.1@3765.47,2924.53 3772.09,2931.14 3772.09,2949.13 3822.96,3000 v1(3960,3000) ; v1@4004.82,3278.28 C18.1@4004.82,3342.85 ; R18.1@4069.53,2570 4119.53,2520 R7.1 ; U2.8@4239.57,2820 4239.57,2879.57 v1(4270,2910) ; C21.1 4266.38,4050.55 v1@4285,4069.18 ; 4289.53,2943.67 4289.53,2929.53 C22.1 ; C22.1@4350.47,2930 C24.2@4430,2930 ; C27.1 4592.4,3120 ; C27.1@4545,3128.98 v1(4545,3245) ; v1(4615,3020) 4655,3060 ; R19.2 4799.42,2653 4864,2653 v1(4867,2656) ; v1@4981.93,3265 C5.2@5040,3265 ; R9.1@5011.97,2879.72 5081.69,2810 v1(5190,2810) 5317.54,2810 5354.82,2847.28 5354.82,2926.08 5343.1,2937.8 C12.2@5295,2937.8 ; C5.1 L3.2@5123.35,3329.06 ; L2.1@5184.29,3485 5192.35,3476.94 v1@5192.35,3447.65 ; v1(5200,3440) 5228.28,3468.28 C4.2@5228.28,3488.76 ; C4.1@5241.76,3561.29 v1(5293.23,3561.29) ; C1.2@5274.69,3926.14 5306.14,3926.14 5316.14,3936.14 v1@5316.14,3965 ; v1(1640,3420) 1643.24,3420 1640,3423.24 v1(1640,3420)
  SIG_1 w25: C35.1 719.53,2889.53 800,2970 800,3052 758.7,3093.3 736.7,3093.3 P1.8 ; C23.1@4725.94,2935 v1(4785,2935)
  SIG_1 w28.7: v1(3920,4180) 3924.08,4175.92 3939.84,4175.92 3962.87,4152.89 C7.2@3986.79,4152.89 ; C7.2@4012.64,4152.32 4013.21,4152.89 4013.21,4155.62 4030.59,4173 4077.24,4173 4080.16,4175.92 v1@4083.04,4173.04 ; v1(4090,4180) 4150,4120
  SIG_1 w30: v1(5807,3424) 5810.75,3420.25 5810.75,3383.17 ; v1(5810,3280) U6.2@5810,3330
  SIG_1 w39.87: C8.2 3712.94,3905 v1(3767.97,3960.03) ; v1@3776.5,3960.03 3800.52,3984.06 C6.2
  SIG_1 w40: C21.1@4275.6,4010 v1@4294.52,4010
  SIG_1 w42: v1(4340,3340) C33.1
  SIG_1 w44: v1@4011.04,3275.18 4036.21,3250 C20.1@4110,3250
  SIG_1 w55: C34.1@4340,3915 v1(4340,3950)
  GND w10: v2(3945.04,3585.04) v2(3988.35,3585.04) v2(4031.65,3585.04) ; v2(4031.65,3671.65) v2(4074.96,3671.65) v2(4074.96,3628.35) v2(4031.65,3628.35) ; v2(4074.96,3585.04) v2(4031.65,3585.04) ; v2(4074.96,3714.96) v2(4031.65,3714.96) v2(3988.35,3714.96) ; v2(3945.04,3714.96) 3921.73,3714.96 3915.87,3709.1 3915.87,3700.82 v2(3945.04,3671.65) v2(3945.04,3628.35) v2(3988.35,3628.35) v2(4031.65,3628.35) ; v2(3945.04,3714.96) v2(3988.35,3671.65) v2(3988.35,3714.96) ; v2(3945.04,3714.96) v2(3988.35,3714.96) ; v2(4031.65,3585.04) v2(4031.65,3628.35)
  other v1: 3557,2925 4910,3990 4305,4010
  other v3: 4690,3070.47 4690,3099.41 4690,3129.53
NetC1_1: C1.1 L1.2 R1.1 | length 114.3
  SIG_1 w10: L1.2 L1.2@5242.28,4021.57 ; C1.1@5252.59,3962.12 C1.1 C1.1@5260,3970.51
  SIG_1 w20: L1.2 5240.71,3989.8 C1.1@5260,3970.51 ; L1.2@5242.28,4021.57 R1.1
NetC2_1: C2.1 C11.1 C13.2 | length 1195.7
  SIG_1 w20: C2.1@4910,3639.53 4910,3710 4870,3750 4870,3790 4950,3870 4950,3910 4910,3950 4910,3970
  SIG_1 w37.95: 4405,3639.53 C2.1@4910,3639.53
  SIG_1 w40: 4465,3322.06 4465,3616.06
NetC2_2: C2.2 D1.2 L1.1 | length 638.2
  SIG_1 w10: C2.2 C2.2@4970.53,3639
  SIG_1 w20: D1.2 5119,3701 5090,3730 5090,3750 5160,3820 5160,3840 5080,3920 5080,3940 5160,4020
  SIG_1 w37.95: C2.2@4970.53,3639 D1.2
NetC3_1: C3.1 D1.1 L2.2 | length 160.4
  SIG_1 w10: L2.2 L2.2@5175,3565.71
  SIG_1 w20: L2.2@5175,3565.71 D1.1
  SIG_1 w37.95: D1.1@5180,3639.53 C3.1
NetC3_2: C3.2 C10.2 U6.3 | length 1063.7
  SIG_1 w37.95: C10.2 5399.53,3089.53 5460,3150 5460,3355 ; C3.2 5395.47,3639.53 5460,3575 5460,3355 ; 5765.06,3355 5460,3355
NetC6_1: C6.1 U1.6 | length 186.8
  SIG_1 w10: C6.1@3865,3920 C6.1
  SIG_1 w25: U1.6@3865,3740.28 C6.1@3865,3920
NetC7_1: C7.1 P1.2 R17.1 U1.5 | length 227.8
  SIG_1 w10: R17.1 4414.61,2650 v1(4470,2650)
  SIG_1 w25: U1.5@3917.17,3792.44 3917.28,3792.55 3917.28,3897.28 v1(3960,3940)
  other v1: 4470,2560 4560,2560 4560,2650 4030,3940 3960,4010 4030,4010
NetC8_1: C8.1 R2.2 R4.1 | length 192.1
  SIG_1 w10: C8.1@3590.2,3890.24 3604.96,3905 C8.1
  SIG_1 w39.87: R2.2@3520,3905 3590.2,3905 C8.1@3604.96,3905 ; R4.1 C8.1@3590.2,3890.24
NetC9_1: C9.1 U4.2 | length 219.2
  SIG_1 w10: U4.2@4721.52,3089.41 4721.63,3089.53 4761.47,3089.53 4762,3089
  SIG_1 w37.95: 4777,3089.53 C9.1
NetC9_2: C9.2 D2.1 L3.1 | length 287
  SIG_1 w10: D2.1@5119.53,3089.53 D2.1
  SIG_1 w39.87: C9.2 D2.1@5119.53,3089.53 ; D2.1 L3.1
NetC10_1: C10.1 D2.2 L4.2 | length 241.6
  SIG_1 w10: D2.2 D2.2@5184.94,3095 ; C10.1@5254.53,3095 C10.1
  SIG_1 w37.95: L4.2 5200,3079.94 5184.94,3095 C10.1@5254.53,3095
NetC11_2: C11.2 C13.1 C16.2 C17.2 C20.2 C21.2 C33.2 C34.2 U1.16 U1.17 U1.18 U1.19 U1.20 | length 880.5
  SIG_1 w10: 4350,3550 4350.51,3549.49 ; 4350,3730 4350.47,3729.53
  SIG_1 w28.7: C17.2@4147.5,4010 4147.5,3952.5 4187.5,3912.5 4237.5,3912.5 4257.5,3892.5 4257.5,3847.5 4222.5,3812.5 ; C17.2@4170,4010 C21.2@4200,4010
  SIG_1 w42: C33.2 4340,3480
  SIG_1 w44: C20.2@4190,3250 4250,3250 4280,3280 4280,3320 4240,3360 4190,3360 4170,3380 4170,3425 4205,3460 ; 4350.47,3729.53 C11.2@4390,3729.53 ; 4350.51,3549.49 C13.1@4390,3549.49
  SIG_1 w55: 4340,3780 C34.2@4340,3830
NetC12_1: C12.1 L4.1 R8.1 | length 191.7
  SIG_1 w10: R8.1 5112.95,2895.47 5128.9,2879.53 ; L4.1 L4.1@5200.2,2879.72
  SIG_1 w20: 5128.9,2879.53 L4.1 ; L4.1@5200.2,2879.72 C12.1
NetC14_2: C14.2 R5.1 | length 112.4
  SIG_1 w10: R5.1 3587.6,3522.13 R5.1@3605.47,3504.25
  SIG_1 w20: C14.2@3605.47,3425 R5.1@3605.47,3504.25
NetC15_2: C15.2 R6.2 U1.10 | length 442
  SIG_1 w10: C15.2 C15.2@3665.04,3320 ; 3797.52,3452.48 3800,3450
  SIG_1 w20: C15.2@3665.04,3320 3797.52,3452.48 3865,3519.96 U1.10@3865,3559.17 ; R6.2 3800,3450
NetC18_2: C18.2 U1.11 | length 148.8
  SIG_1 w20: 3917.17,3447.25 3932.1,3432.32 C18.2
  SIG_1 w25: 3917.17,3447.25 U1.11@3917.17,3507.01
NetC19_2: C19.2 R16.2 U2.3 | length 357.5
  SIG_1 w10: C19.2 C19.2@3821.42,2703.11 ; 3994.58,2710 4004.58,2720 U2.3@4025,2720
  SIG_1 w20: C19.2 3994.58,2710 ; R16.2 C19.2@3821.42,2703.11
NetC22_2: C22.2 C23.2 C24.1 C29.2 C30.2 C36.2 C37.2 L5.2 L6.2 M1.2 P1.7 R11.2 U5.5 U5.6 | length 1318.8
  SIG_1 w10: U5.5 1632.82,3271.61 U5.5@1635.47,3268.96 ; 1635,3040 1640,3035 v1(1640,2980) ; v1(3490,2800) C36.2 3575.16,2874.57 3585,2884.41 3663.58,2884.41 L6.2@3675,2872.99 ; C24.1@4441.18,2869.29 C24.1 4539.53,2870.47 L5.2@4540.71,2869.29 ; C23.2@4721.46,2871.46 C23.2 ; M1.2@4832.64,2742.6 M1.2
  SIG_1 w20: U5.5 U5.6@1631.38,3290 ; 1635,3040 C30.2 C29.2@1635,3204.53 ; C29.2 U5.5@1635.47,3268.96 ; v1(4330,2800) 4330,2805.57 4350,2825.57 C22.2 ; C23.2@4730.05,2866.41 4730.05,2845.19 M1.2@4832.64,2742.6
  SIG_1 w25: C22.2 C24.1 ; C24.1@4441.18,2869.29 L5.2 4540.71,2869.29 R11.2@4622.83,2869.29 ; R11.2 C23.2@4721.46,2871.46
NetC25_1: C25.1 U5.1 | length 165.5
  SIG_1 w20: C25.1 1390,3420 U5.1@1455,3355
NetC26_1: C26.1 L5.1 U4.7 | length 206.9
  SIG_1 w10: 4585.35,3089.84 U4.7@4654.49,3089.84
  SIG_1 w37.95: C26.1 4535.01,3040 4547.47,3052.46 4549.54,3052.46 4572.89,3075.82 ; 4535,2955 C26.1@4535,3039.53
NetC26_2: C26.2 C27.2 U7.7 | length 364.2
  SIG_1 w10: U7.7 4230.31,3052.05 4266.95,3052.05 4279,3040 4293.55,3040
  SIG_1 w20: C27.2 4475,3119.02 4467.28,3111.3 4466.3,3111.3 4443.52,3088.52 4443.52,3061.4 4455.24,3049.69 4465.79,3049.69 C26.2
  SIG_1 w37.95: 4293.55,3040 C26.2@4455.24,3040
  SIG_1 w39.87: C26.2@4455.24,3040 C26.2
NetC28_2: C28.2 R13.1 U5.2 | length 205.6
  SIG_1 w10: C28.2 C28.2@1320.35,3347.05
  SIG_1 w20: C28.2@1320.35,3347.05 R13.1 1360.13,3275 1405.13,3320 1409.02,3320 1412.68,3323.66 1429.56,3323.66
NetC31_2: C31.2 R3.2 U2.1 | length 354
  SIG_1 w10: U2.1@4008.27,2820 4025,2820 4031.98,2820 U2.1@4038.27,2826.29 ; R3.2@4090.55,2899.09 R3.2@4090.55,2905
  SIG_1 w20: C31.2 3918.27,2910 U2.1@4008.27,2820 ; U2.1@4038.27,2826.29 4038.27,2846.81 R3.2@4090.55,2899.09
NetC32_2: C32.2 U2.2 | length 214.9
  SIG_1 w20: C32.2@3826.5,2810 3960,2810 4003.19,2766.81 4005,2765 U2.2
NetC35_2: C35.2 P1.1 R10.2 R14.2 | length 5194.8
  SIG_1 w10: C35.2@644.8,2855.67 644.8,2854.69 659.49,2840 C35.2 ; v1(920,3420) R10.2 ; R14.2 4714.45,3340 v1(4800,3340)
  SIG_1 w25: P1.1 630,2870.47 C35.2@644.8,2855.67
  GND-PWR w10: P1.1 638.64,3008.64 675,3008.64 721.53,3055.17 721.7,3055 753,3055 761,3063 766.06,3063
  GND-PWR w20: 766.06,3063 893,3063 1000,3170 1000,3390 970,3420 v1(920,3420)
  SIG_2 w10: v1(920,3420) 1120,3620 3690,3620 3930,3380 4260,3380 4284.14,3404.14 4440,3404.14 4440,3400 4500,3340 v1(4800,3340)
NetC38_1: C38.1 R21.1 R21.2 U1.8 U5.7 | length 5099
  SIG_1 w8.05: 1820,3322.8 1820,3085.77 ccw(c1865,3085.77) 1865,3040.77 2565,3040.77 ccw(c2565,3080.77) 2605,3080.77 R21.1
  SIG_1 w10: U5.7 1678.2,3322.8 1679.82,3321.18 1691.18,3321.18 1692.8,3322.8 ; R21.1 R21.1@2611.16,3299.39 ; 2659.45,3374.45 2675.61,3390.61
  SIG_1 w10.08: 1820,3322.8 1820,3340
  SIG_1 w28.47: 2675.61,3299.39 ccw(c2935,3299.39) 2935,3040 3244.93,3040
  SIG_1 w30: R21.2 2659.45,3374.45 2675,3374.45 ; R21.1@2611.16,3299.39 2675.61,3299.39
  SIG_1 w36.1: 1820,3340 1820,3600 cw(c1865,3600) 1865,3645 ; 1865,3644.41 2565,3644.41 cw(c2565,3604.41) 2587.62,3637.4 2597.99,3627.03 cw(c2565,3604.41) 2605,3604.41 R21.2@2605,3384.41
  SIG_1 w37.95: 1692.8,3322.8 1820,3322.8
  SIG_1 w39.87: 3244.93,3040 3324.93,3040 ; 3265,3650 U1.8
  SIG_1 w50.17: 2675.61,3390.61 cw(c2935,3390.61) 2935,3650 3244.93,3650
NetC38_2: C38.2 C40.2 U8.1 | length 253
  SIG_1 w10: C40.2 3400,3034.49 C38.2 ; U8.1@3548.11,3040 3556.89,3048.78 U8.1
  SIG_1 w37.95: C38.2 U8.1@3548.11,3040
NetC39_1: C39.1 L6.1 U8.3 | length 288.5
  SIG_1 w10: L6.1@3675,2947.01 U8.3
  SIG_1 w37.95: U8.3@3680,3055 C39.1
NetC39_2: C39.2 C41.2 U7.2 | length 201.8
  SIG_1 w10: C39.2 C41.2 ; 3998.92,3055 4001.13,3052.8 U7.2
  SIG_1 w37.95: C39.2 3998.92,3055
NetE1_1: E1.1 R18.2 R19.1 R20.2 U2.4 U2.7 | length 1231.4
  SIG_1 w10: U2.4@4011.46,2663.71 U2.4@4017.75,2670 ; E1.1@4723.58,2582.52 4764.55,2541.55 E1.1@4739.46,2516.46 ; R19.1 R19.1@4723.58,2655.91
  SIG_1 w15: R20.2 E1.1@4739.46,2516.46
  SIG_1 w20: R18.2 U2.4@4011.46,2663.71 ; U2.4@4017.75,2670 4085,2670 4185,2770 4280,2770 4300,2750 4629.49,2750 R19.1@4723.58,2655.91 ; E1.1@4723.58,2582.52 R19.1
NetM1_1: M1.1 P1.9 R1.2 | length 5869.2
  SIG_1 w20: M1.1 4840.51,2890.51 v1(4880,2930) ; R1.2 5400.31,4021.57 5421.88,4000 v1(5430,4000)
  SIG_2 w10: P1.9 736.82,3206.82 1026.82,3206.82 1070,3250 1890,3250 2100,3040 4196.57,3040 4341.57,2895 4845,2895 v1(4880,2930) 4880,3460 5420,4000 v1(5430,4000)
NetM1_3: M1.3 R8.2 R9.2 | length 295.8
  SIG_1 w10: R9.2@5008.03,2942.72 R9.2 R9.2@5011.97,2944.68
  SIG_1 w20: M1.3 4935,2869.68 R9.2@5008.03,2942.72 ; R9.2@5011.97,2944.68 R8.2
NetP1_3: P1.3 R14.1 U4.5 | length 5266.2
  SIG_1 w10: U4.5 4659.67,3129.53 4660.58,3130.43 4660.58,3144.58 4673.37,3157.37 4673.37,3243.26 4688.43,3258.31 4688.43,3259.88 4704.09,3275.55 R14.1 4725.55,3260 v1(4800,3260)
  GND-PWR w10: P1.3 675,3155 845,3155 v1(850,3160)
  SIG_2 w10: v1(850,3160) 845,3155 675,3155 P1.3 639.57,3209.57 659.57,3209.57 700,3250 781.72,3250 911.72,3380 1143.43,3380 1293.43,3530 2350,3530 2650,3230 3251.72,3230 3321.72,3300 3923.43,3300 3988.25,3235.18 4292.37,3235.18 4342.19,3285 4646.3,3285 4671.3,3260 v1(4800,3260)
NetP1_4: P1.4 U5.4 | length 1544.4
  SIG_1 w15: v1(1430,3080) 1430,3086.29 1450,3106.29 U5.4@1450,3271.83
  SIG_2 w10: P1.4 550,3220 550,2960 600,2910 800,2910 930,3040 1390,3040 v1(1430,3080)
NetP1_11: P1.11 R2.1 | length 85.6
  SIG_1 w10: R2.1@3438.5,3900 R2.1
  SIG_1 w20: v1(3360,3900) R2.1@3438.5,3900
NetP1_12: P1.12 R6.1 | length 92.3
  SIG_1 w20: R6.1 3802.78,3262.78 3887.22,3262.78 v1(3890,3260)
NetP2_1: P2.1 P2.2 R20.1 | length 287.9
  SIG_1 w10: R20.1 R20.1@4797.54,2348
  SIG_1 w15: R20.1@4797.54,2348 P2.1 P2.2
NetR3_1: R3.1 U7.5 | length 125.7
  SIG_1 w10: R3.1@4159.45,2905 R3.1@4159.45,2910.91
  SIG_1 w20: R3.1@4159.45,2910.91 4229.57,2981.02 U7.5
NetR4_2: R4.2 U1.7 | length 245.6
  SIG_1 w25: R4.2 3695,3805 3805,3695 U1.7@3865,3695
NetR5_2: R5.2 U1.9 | length 238
  SIG_1 w10: R5.2 R5.2@3662.4,3537.87
  SIG_1 w20: R5.2@3662.4,3537.87 3728.98,3604.45 U1.9@3865,3604.45
NetR7_2: R7.2 R17.2 U2.5 U2.6 | length 275.7
  SIG_1 w10: U2.6@4239.57,2720 4239.57,2670 U2.5@4259.99,2670 ; R17.2@4360,2654.61 R17.2
  SIG_1 w20: U2.5 4255,2665 4265,2655 R17.2 ; R7.2 R17.2@4360,2654.61
NetR10_1: R10.1 R12.2 R13.2 U3.2 | length 377.3
  SIG_1 w10: R13.2@1246.54,3264.17 R13.2 R13.2@1257.36,3276.97
  SIG_1 w20: R10.1 1064.45,3362.44 U3.2 1226.93,3307.4 R13.2@1257.36,3276.97 ; R12.2 R13.2@1246.54,3264.17
NetR11_1: R11.1 U4.1 | length 180.1
  SIG_1 w10: R11.1 4631.39,2934.93 4631.39,2956.39 4720,3045 U4.1@4720,3069.25
NetR12_1: R12.1 R15.2 U3.1 | length 335.5
  SIG_1 w10: U3.1 1127.36,3232.6 U3.1@1134.17,3225.79 ; 1256.67,3110 1257.36,3110 ; R12.1@1298.58,3175.12 R12.1
  SIG_1 w20: U3.1@1134.17,3225.79 1134.17,3165.83 1165,3135 1243.95,3135 ; 1256.67,3110 1243.95,3122.72 1243.95,3135 ; R12.1@1298.58,3175.12 1298.58,3154.28 1279.3,3135 1243.95,3135
NetU6_1: U6.1 | length 118
  SIG_1 w44: 5860,3355 5978,3355

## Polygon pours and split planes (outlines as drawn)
NetC11_2 on SIG_1 "NETC11_2_L01_P007" (solid, pour order 7): 4205,3810 4360,3810 4360,3460 4205,3460 4140,3525 4140,3745
NetC7_1 on SIG_1 "NETC7_1_L01_P026" (solid, pour order 26): 3910,4110 4090,4110 4090,3850 3910,3850
NetC7_1 on SIG_1 "NETC7_1_L01_P008" (solid, pour order 8): 4400,2720 4610,2720 4610,2480 4400,2480
NetC7_1 on GND-PWR "NETC7_1_L03_P012" (solid, pour order 12): 4400,2750 4400,3380 3860,3920 3860,4090 4160,4090 4680,3570 4680,2750
NetP1_12 on GND-PWR "NETP1_12_L03_P023" (solid, pour order 23): 3950,3170 3950,3410 3770,3590 680,3590 680,3450 3640,3450 3760,3330 3760,3170
NetC22_2 on GND-PWR "NETC22_2_L03_P022" (solid, pour order 22): 4360,2770 740,2770 700,2810 700,3028 1722,3028 1890,2860 4360,2860
NetC7_1 on GND-PWR "NETC7_1_L03_P021" (solid, pour order 21): 4680,2750 4680,2470 4660,2450 640,2450 505,2585 505,3150 640,3150 640,2750
NetP1_11 on SIG_2 "NETP1_11_L04_P024" (solid, pour order 24): 3420,3960 3420,3810 1140,3810 800,3350 680,3350 680,3450 1050,3960 1100,3960
GND on GND "GND_L02_P003" (solid, pour order 3): 505,4245 6010,4245 6010,2270 505,2270

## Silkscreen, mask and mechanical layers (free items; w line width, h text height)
Board Outline:
  lines w10: 505,2270 505,4245 6010,4245 6010,2860 6010,2270 5950,2270 505,2270
Fab Notes:
  lines w10: 1030,3440 2000,3440 ; 1030,3600 2000,3600 ; 1030,3685.07 2000,3685.07 ; 1030,3770 2000,3770 ; 1030,3950 2000,3950 ; 1300,3550 1300,3540 1250,3490 1190,3490 1250,3550 1240,3550 1230,3550 1200,3550 1190,3540 1140,3490 1090,3490 1150,3550 1100,3550 1040,3490 1030,3490 ; 1300,3890 1300,3880 1250,3830 1190,3830 1250,3890 1240,3890 1230,3890 1200,3890 1190,3880 1140,3830 1090,3830 1150,3890 1100,3890 1040,3830 1030,3830 ; 1310,3490 1370,3550 ; 1310,3830 1370,3890 ; 1360,3490 1420,3550 ; 1360,3830 1420,3890 ; 1410,3490 1465,3545 ; 1410,3830 1465,3885 ; 1460,3490 1520,3550 ; 1460,3830 1520,3890 ; 1520,3490 1580,3550 ; 1520,3830 1580,3890 ; 1580,3490 1640,3550 ; 1580,3830 1640,3890 ; 1630,3490 1690,3550 ; 1630,3830 1690,3890 ; 1680,3490 1730,3540 ; 1680,3830 1730,3880 ; 1730,3490 1790,3550 ; 1730,3830 1790,3890 ; 1790,3490 1840,3540 ; 1790,3830 1840,3880 ; 1840,3490 1900,3550 ; 1840,3830 1900,3890 ; 1890,3490 1950,3550 ; 1890,3830 1950,3890 ; 1950,3490 2000,3540 ; 1950,3830 2000,3880 ; 1030,3490 2000,3490 2000,3550 1030,3550 1030,3490 ; 1030,3830 2000,3830 2000,3890 1030,3890 1030,3830 ; 1030,3670 2000,3670 2000,3700.14 1030,3700.14 1030,3670
  text "1. Board to be FR4 with relative dielectric constant of 4.45 +/- 10%" at 640,4890 h60
  text "2. Dielectric thickness between LYR 1 & 2 to be 20 mils." at 640,4800 h60
  text "3. All through-holes and vias to be plated." at 640,4709.99 h60
  text "4. Copper weight of all layers to be 2 Oz." at 640,4619.99 h60
  text "2 OZ" at 780,3930 h50
  text "LAYER 1 - RF SIGNAL" at 2050,3930 h50
  text "20 MILS" at 640,3840 h50
  text "DIELECTRIC 1" at 2050,3840 h50
  text "2 OZ" at 780,3750 h50
  text "LAYER 2 - GND" at 2050,3750 h50
  text "PREPREG" at 2050,3660 h50
  text "2 OZ" at 770,3580 h50
  text "LAYER 3 - PWR/GND" at 2050,3580 h50
  text "60 MILS" at 630,3500 h50
  text "DIELECTRIC 2" at 2050,3500 h50
  text "LAYER 4 - SIGNAL" at 2050,3420 h50
  text "2 OZ" at 770,3400 h50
